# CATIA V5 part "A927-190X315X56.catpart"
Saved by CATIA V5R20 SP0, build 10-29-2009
Part number: A927-190X315X56
Source: Unknown
Property "A": "90.000"
Property "ARTICLENO": "A927-190X315X56"
Property "BOMINFO": "A927-190X315X56"
Property "CODE": "A927-190X315X56"
Property "CREATOR": "CADENAS GmbH"
Property "D": "22.000"
Property "D1": "33.000"
Property "F": "36.000"
Property "FORM": "B"
Property "L": "315.000"
Property "L1": "150.000"
Property "L2": "40.000"
Property "L3": "80.000"
Property "LINA": "A927-190X315X56"
Property "NB": "A927-190X315X56"
Property "NBSYN": "$CODE."
Property "NN": "A927"
Property "NT": "VDI 3387 Removable Die Heels, steel and self-lubricating"
Property "R": "31.500"
Property "S": "56.000"
Property "SUPPLIER": "CF"
Property "T": "25.500"
Property "W": "190.000"
Bounding box of the stored display mesh (mm): x -95 to 95, y 0 to 315, z -56 to 0
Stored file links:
  C:\Users\borellobunino\Desktop\3D X SITO CF\A927\GSB_OILLESS_G2290519031556\CATIAV5\A927-190X315X56.catpart
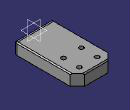
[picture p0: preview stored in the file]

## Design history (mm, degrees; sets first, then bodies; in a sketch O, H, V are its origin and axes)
Body1 "Geometry.1" (main body)
  Solid1 "A927-190X315X56.catpart": solid without history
